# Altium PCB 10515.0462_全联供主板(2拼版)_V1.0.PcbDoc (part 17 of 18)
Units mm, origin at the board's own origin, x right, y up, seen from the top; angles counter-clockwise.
Board outline 282 x 198 mm, 2 copper layers (Top Layer, Bottom Layer); 716 components, 0 nets, 2364 pads, 1800 vias.
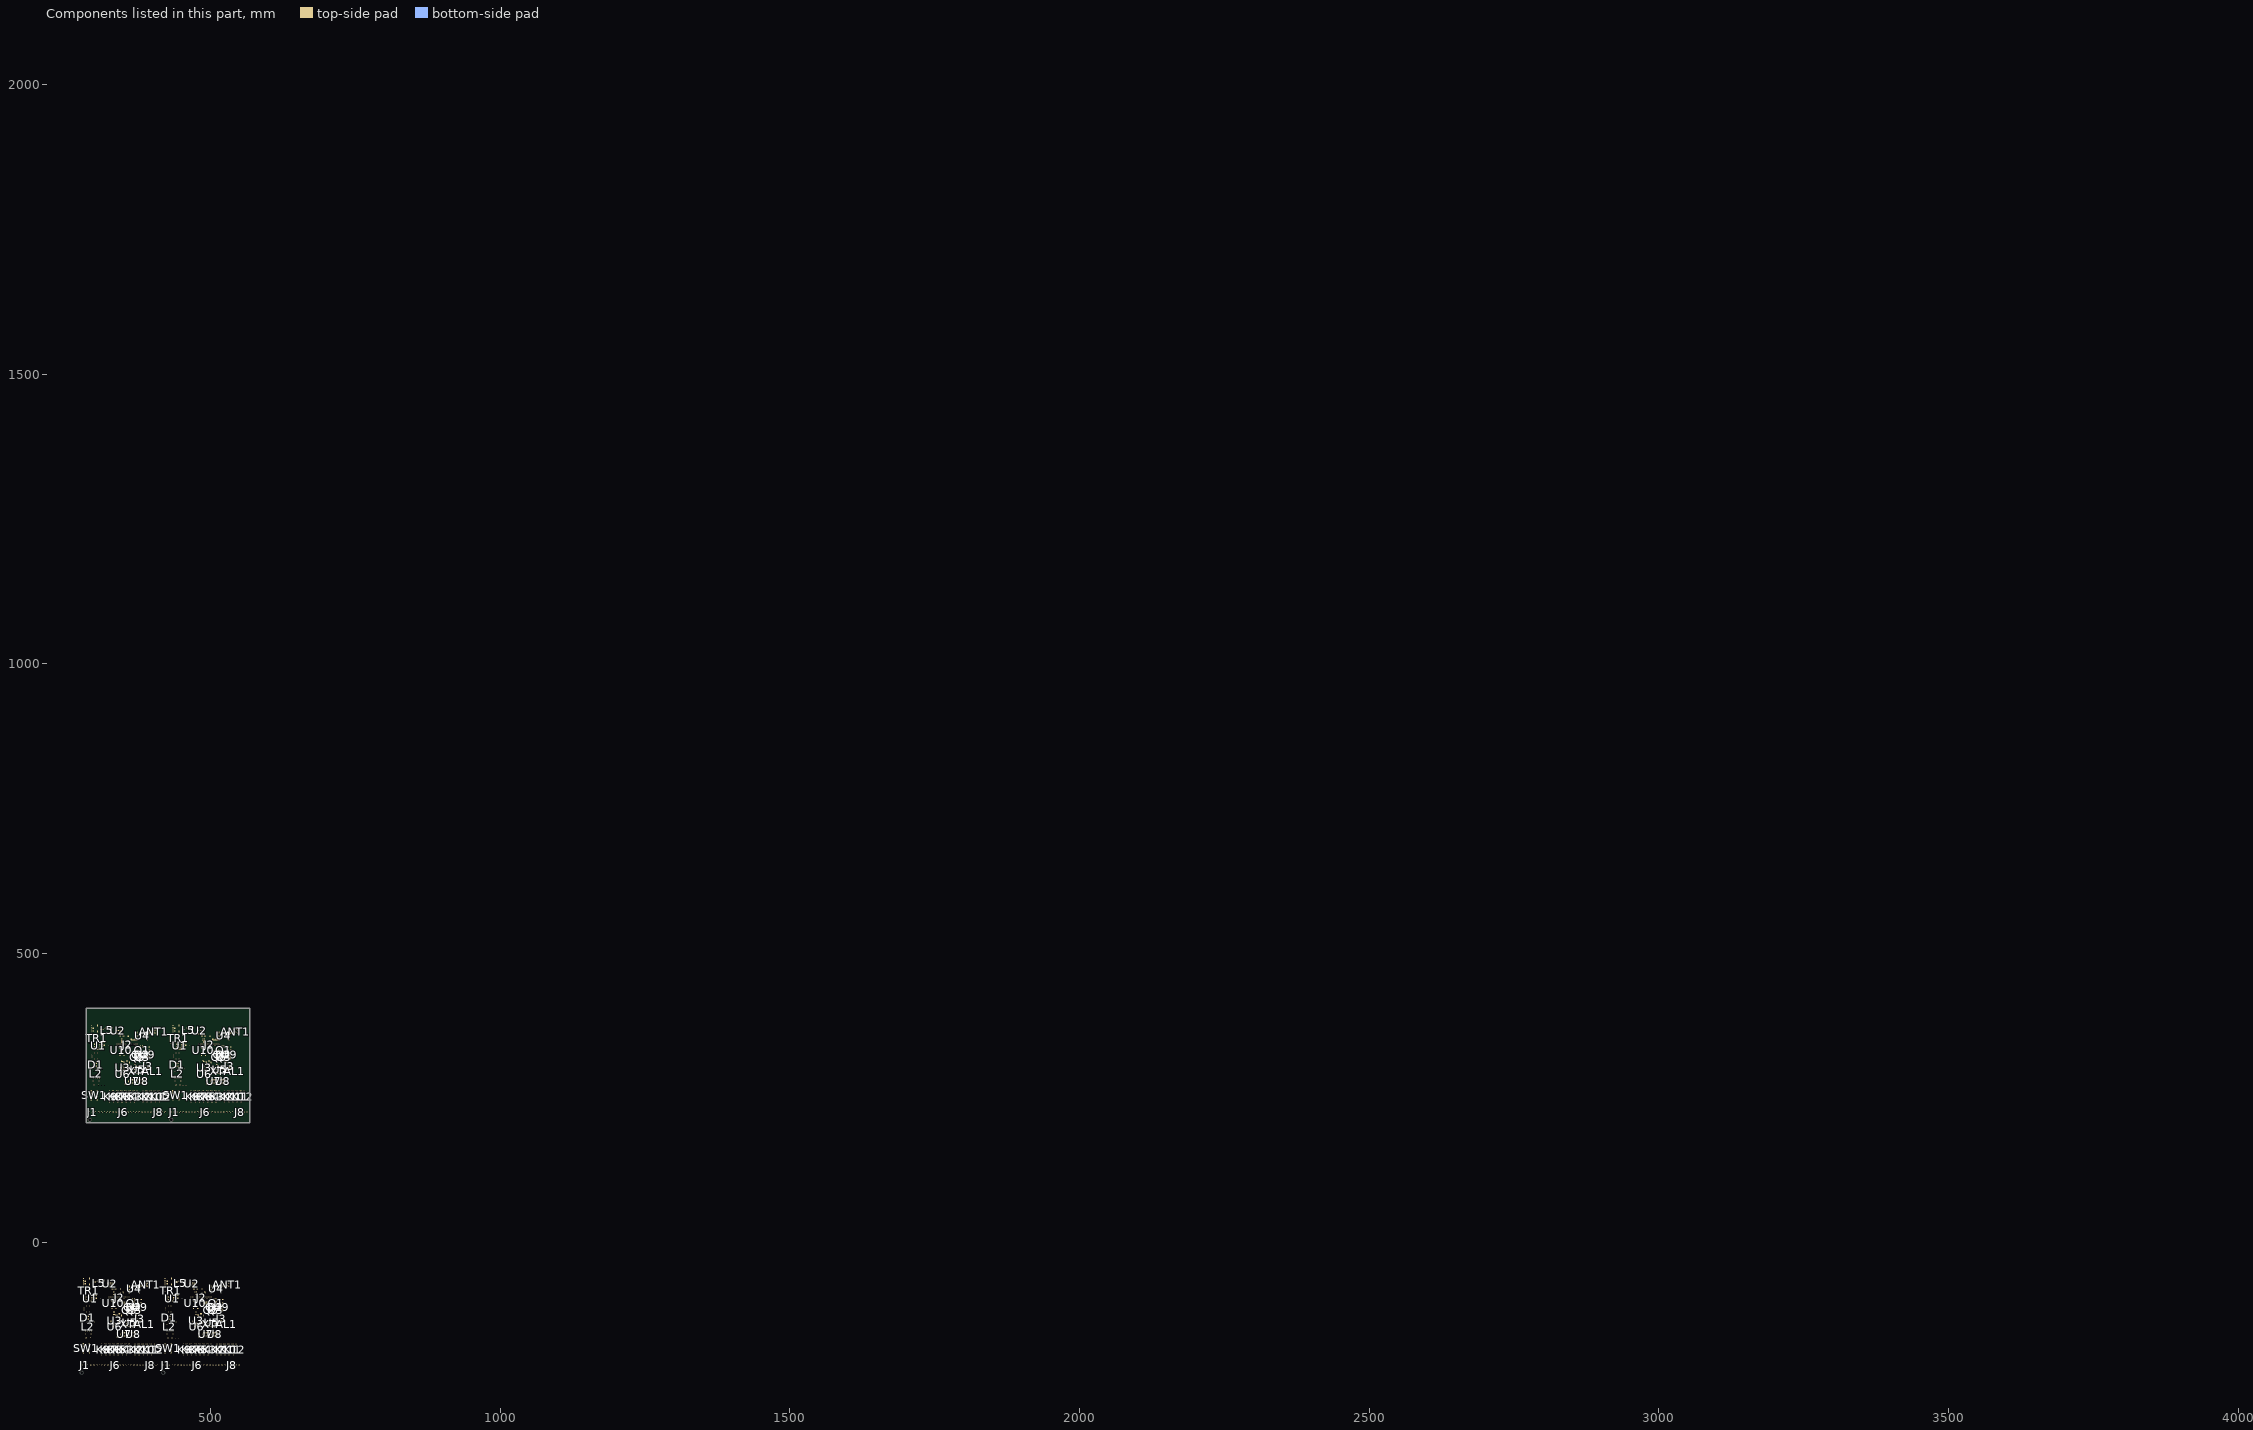
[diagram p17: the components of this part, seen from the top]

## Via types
v1: diameter 0.7, hole 0.4, Top Layer to Bottom Layer, tented both sides, 1800 vias

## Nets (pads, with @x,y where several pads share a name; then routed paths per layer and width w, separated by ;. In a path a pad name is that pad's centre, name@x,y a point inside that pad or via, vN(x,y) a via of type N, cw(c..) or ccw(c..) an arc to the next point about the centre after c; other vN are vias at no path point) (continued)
copper on no net: (continued)
  other v1: 333.609,-159.665 334.371,-159.665 474.609,-159.665 475.371,-159.665 333.99,-158.903 474.99,-158.903 371.943,-153.442 376.281,-153.442 512.943,-153.442 517.281,-153.442 326.731,-153.315 467.731,-153.315 379.837,-153.162 383.774,-153.162 520.837,-153.162 524.774,-153.162 332.319,-153.061 473.319,-153.061 338.923,-152.934 479.923,-152.934 369.403,-152.172 510.403,-152.172 324.191,-151.918 465.191,-151.918 345.527,-151.537 486.527,-151.537 386.441,-151.13 527.441,-151.13 374.63,-150.622 380.853,-150.622 515.63,-150.622 521.853,-150.622 338.923,-150.394 479.923,-150.394 330.688,-150.114 471.688,-150.114 345.801,-148.59 486.801,-148.59 338.181,-148.362 355.453,-148.362 372.959,-148.362 376.281,-148.362 479.181,-148.362 496.453,-148.362 513.959,-148.362 517.281,-148.362 368.387,-148.235 509.387,-148.235 327.259,-148.082 343.134,-148.082 352.405,-148.082 468.259,-148.082 484.134,-148.082 493.405,-148.082 348.575,-147.854 489.575,-147.854 379.563,-147.473 383.627,-147.473 520.563,-147.473 524.627,-147.473 323.175,-147.219 464.175,-147.219 385.806,-147.066 526.806,-147.066 348.067,-146.076 489.067,-146.076 345.527,-145.822 486.527,-145.822 328.021,-145.542 469.021,-145.542 350.373,-145.314 491.373,-145.314 354.437,-145.034 495.437,-145.034 341.229,-144.78 482.229,-144.78 367.01,-144.526 508.01,-144.526 345.166,-144.018 486.166,-144.018 339.939,-143.79 480.939,-143.79 340.955,-143.663 481.955,-143.663 324.338,-143.51 371.582,-143.51 465.338,-143.51 512.582,-143.51 344.511,-143.282 485.511,-143.282 386.167,-143.155 527.167,-143.155 341.737,-143.002 350.754,-143.014 366.375,-143.002 482.737,-143.002 491.754,-143.014 507.375,-143.002 377.297,-142.774 518.297,-142.774 368.151,-142.335 509.151,-142.335 355.818,-142.292 496.818,-142.292 327.747,-142.139 468.747,-142.139 380.091,-142.012 521.091,-142.012 348.341,-140.869 489.341,-140.869 352.913,-140.742 493.913,-140.742 331.303,-139.726 472.303,-139.726 357.485,-139.446 362.438,-139.446 498.485,-139.446 503.438,-139.446 323.83,-138.938 464.83,-138.938 338.415,-138.71 479.415,-138.71 341.971,-138.583 482.971,-138.583 359.009,-138.456 500.009,-138.456 361.168,-138.43 502.168,-138.43 356.469,-138.329 497.469,-138.329 377.424,-137.922 518.424,-137.922 331.303,-137.567 472.303,-137.567 380.98,-137.059 521.98,-137.059 357.993,-136.906 386.314,-136.906 498.993,-136.906 527.314,-136.906 361.93,-136.805 502.93,-136.805 356.469,-136.398 360.152,-136.398 497.469,-136.398 501.152,-136.398 323.175,-136.043 464.175,-136.043 357.866,-135.154 498.866,-135.154 342.987,-135.027 345.019,-135.027 483.987,-135.027 486.019,-135.027 361.295,-134.646 502.295,-134.646 323.683,-134.011 464.683,-134.011 345.928,-133.858 347.706,-133.858 486.928,-133.858 488.706,-133.858 356.703,-133.63 497.703,-133.63 359.751,-133.503 500.751,-133.503 344.15,-133.35 362.819,-133.35 485.15,-133.35 503.819,-133.35 353.548,-132.842 355.326,-132.842 494.548,-132.842 496.326,-132.842 353.929,-131.318 494.929,-131.318 370.378,-130.709 511.378,-130.709 365.867,-130.302 386.06,-130.302 506.867,-130.302 527.06,-130.302 364.47,-129.976 505.47,-129.976 347.198,-128.804 488.198,-128.804 376.154,-128.778 517.154,-128.778 353.655,-128.677 494.655,-128.677 346.182,-127.28 487.182,-127.28 284.587,-126.487 285.222,-126.487 425.587,-126.487 426.222,-126.487 323.175,-126.391 328.255,-126.391 464.175,-126.391 469.255,-126.391 381.742,-125.73 522.742,-125.73 365.232,-125.222 506.232,-125.222 386.167,-123.851 527.167,-123.851 377.805,-123.698 518.805,-123.698 327.386,-123.19 468.386,-123.19 365.486,-122.682 506.486,-122.682 382.103,-122.454 523.103,-122.454 336.784,-120.65 477.784,-120.65 327.513,-120.142 346.436,-120.142 468.513,-120.142 487.436,-120.142 337.673,-119.634 478.673,-119.634 341.463,-118.898 482.463,-118.898 342.88,-118.618 483.88,-118.618 327.513,-117.602 468.513,-117.602 340.447,-116.993 481.447,-116.993 322.941,-116.866 463.941,-116.866 336.383,-116.231 477.383,-116.231 338.923,-115.723 479.923,-115.723 343.007,-115.57 346.69,-115.57 484.007,-115.57 487.69,-115.57 382.123,-115.062 523.123,-115.062 327.005,-114.046 468.005,-114.046 385.659,-113.183 526.659,-113.183 323.068,-112.014 376.789,-112.014 464.068,-112.014 517.789,-112.014 381.869,-111.506 522.869,-111.506 336.657,-109.754 477.657,-109.754 326.878,-108.966 467.878,-108.966 373.614,-107.95 514.614,-107.95 322.667,-106.579 463.667,-106.579 358.501,-105.918 359.771,-105.918 499.501,-105.918 500.771,-105.918 327.239,-105.182 372.959,-105.182 468.239,-105.182 513.959,-105.182 382.123,-104.902 523.123,-104.902 386.167,-104.039 527.167,-104.039 335.514,-103.658 476.514,-103.658 322.941,-102.362 327.005,-102.362 336.657,-102.362 463.941,-102.362 468.005,-102.362 477.657,-102.362 359.009,-101.346 500.009,-101.346 361.783,-101.245 502.783,-101.245 382.377,-100.838 523.377,-100.838 380.579,-100.356 521.579,-100.356 373.467,-100.229 514.467,-100.229 327.239,-100.102 468.239,-100.102 336.657,-99.975 477.657,-99.975 322.667,-98.705 463.667,-98.705 382.611,-96.038 523.611,-96.038 380.853,-95.25 386.314,-95.25 521.853,-95.25 527.314,-95.25 362.565,-92.202 503.565,-92.202 377.023,-92.101 518.023,-92.101 366.355,-91.974 373.741,-91.974 507.355,-91.974 514.741,-91.974 381.087,-91.847 522.087,-91.847 369.804,-91.696 510.804,-91.696 379.055,-90.196 520.055,-90.196 325.989,-89.688 466.989,-89.688 329.271,-89.307 470.271,-89.307 346.436,-88.63 487.436,-88.63 345.227,-88.415 349.083,-88.418 486.227,-88.415 490.083,-88.418 323.83,-88.291 341.483,-88.291 464.83,-88.291 482.483,-88.291 350.5,-88.138 358.882,-88.138 371.074,-88.138 377.932,-88.138 491.5,-88.138 499.882,-88.138 512.074,-88.138 518.932,-88.138 355.687,-88.037 496.687,-88.037 348.067,-87.91 489.067,-87.91 345.846,-87.796 486.846,-87.796 361.275,-87.783 502.275,-87.783 353.929,-87.63 494.929,-87.63 342.245,-87.529 483.245,-87.529 350.099,-87.255 491.099,-87.255 379.964,-87.122 520.964,-87.122 337.399,-86.894 478.399,-86.894 327.894,-86.614 365.994,-86.614 468.894,-86.614 506.994,-86.614 371.943,-86.259 512.943,-86.259 362.184,-86.106 503.184,-86.106 339.451,-85.09 480.451,-85.09 323.957,-84.608 464.957,-84.608 380.091,-84.582 521.091,-84.582 346.436,-84.163 487.436,-84.163 371.074,-84.13 512.074,-84.13 363.835,-84.074 367.645,-84.074 504.835,-84.074 508.645,-84.074 335.875,-83.846 476.875,-83.846 344.912,-83.566 485.912,-83.566 380.071,-83.338 521.071,-83.338 326.243,-83.211 467.243,-83.211 339.578,-83.058 349.103,-83.058 480.578,-83.058 490.103,-83.058 354.056,-82.957 495.056,-82.957 329.291,-82.83 470.291,-82.83 303.764,-82.576 444.764,-82.576 344.912,-82.55 485.912,-82.55 302.621,-82.195 443.621,-82.195 350.607,-81.941 372.451,-81.941 491.607,-81.941 513.451,-81.941 303.637,-81.814 304.272,-81.814 444.637,-81.814 445.272,-81.814 352.532,-81.687 370.419,-81.687 493.532,-81.687 511.419,-81.687 302.958,-81.643 443.958,-81.643 335.26,-81.534 476.26,-81.534 347.559,-81.433 380.071,-81.433 488.559,-81.433 521.071,-81.433 339.431,-81.179 365.847,-81.179 480.431,-81.179 506.847,-81.179 336.784,-81.026 477.784,-81.026 302.494,-80.925 443.494,-80.925 355.58,-80.518 496.58,-80.518 363.073,-80.01 369.169,-80.01 504.073,-80.01 510.169,-80.01 349.083,-79.909 490.083,-79.909 365.232,-79.502 380.345,-79.502 506.232,-79.502 521.345,-79.502 323.576,-79.401 464.576,-79.401 327.005,-79.274 339.431,-79.274 468.005,-79.274 480.431,-79.274 347.198,-78.486 488.198,-78.486 375.499,-78.385 516.499,-78.385 355.687,-78.004 496.687,-78.004 350.246,-77.978 372.598,-77.978 491.246,-77.978 513.598,-77.978 377.023,-77.75 380.071,-77.75 518.023,-77.75 521.071,-77.75 339.832,-77.47 353.294,-77.47 370.439,-77.47 480.832,-77.47 494.294,-77.47 511.439,-77.47 373.614,-76.962 383.393,-76.962 387.457,-76.962 389.997,-76.962 391.902,-76.962 514.614,-76.962 524.393,-76.962 528.457,-76.962 530.997,-76.962 532.902,-76.962 385.151,-76.833 526.151,-76.833 344.003,-76.734 381.087,-76.734 485.003,-76.734 522.087,-76.734 386.568,-76.48 527.568,-76.48 336.784,-76.454 379.329,-76.454 477.784,-76.454 520.329,-76.454 362.565,-76.226 503.565,-76.226 376.007,-76.099 517.007,-76.099 367.264,-75.946 377.805,-75.946 508.264,-75.946 518.805,-75.946 347.051,-75.718 382.611,-75.718 387.691,-75.718 393.045,-75.718 488.051,-75.718 523.611,-75.718 528.691,-75.718 534.045,-75.718 341.737,-75.438 377.043,-75.438 482.737,-75.438 518.043,-75.438 378.44,-74.956 519.44,-74.956 351.389,-74.93 492.389,-74.93 382.631,-74.917 523.631,-74.917 380.579,-74.829 521.579,-74.829 354.163,-74.702 355.687,-74.702 495.163,-74.702 496.687,-74.702 387.076,-74.482 388.092,-74.482 528.076,-74.482 529.092,-74.482 374.884,-74.422 392.918,-74.422 515.884,-74.422 533.918,-74.422 364.089,-74.194 382.611,-74.194 505.089,-74.194 523.611,-74.194 369.911,-74.067 510.911,-74.067 378.44,-73.94 519.44,-73.94 332.72,-73.914 351.262,-73.914 473.72,-73.914 492.262,-73.914 373.467,-73.813 514.467,-73.813 349.23,-73.406 490.23,-73.406 332.085,-73.178 473.085,-73.178 382.814,-73.152 523.814,-73.152 338.923,-73.051 378.44,-73.051 392.771,-73.051 479.923,-73.051 519.44,-73.051 533.771,-73.051 375.349,-72.898 516.349,-72.898 374.483,-72.67 515.483,-72.67 341.971,-72.543 482.971,-72.543 371.836,-72.39 393.553,-72.39 512.836,-72.39 534.553,-72.39 390.113,-72.289 531.113,-72.289 336.149,-72.162 347.051,-72.162 477.149,-72.162 488.051,-72.162 391.247,-72.035 532.247,-72.035 351.897,-71.882 354.437,-71.882 365.232,-71.882 492.897,-71.882 495.437,-71.882 506.232,-71.882 322.944,-71.522 463.944,-71.522 390.113,-71.4 531.113,-71.4 356.596,-71.374 374.757,-71.374 497.596,-71.374 515.757,-71.374 334.351,-71.019 475.351,-71.019 392.283,-70.866 533.283,-70.866 382.611,-70.669 523.611,-70.669 393.279,-70.638 534.279,-70.638 375.9,-70.556 377.805,-70.556 516.9,-70.556 518.805,-70.556 374.991,-70.003 515.991,-70.003 377.023,-69.876 518.023,-69.876 336.276,-69.85 377.805,-69.85 477.276,-69.85 518.805,-69.85 382.585,-69.622 523.585,-69.622 386.949,-69.402 387.965,-69.402 527.949,-69.402 528.965,-69.402 378.694,-69.284 519.694,-69.284 318.496,-69.114 320.655,-69.114 459.496,-69.114 461.655,-69.114 334.859,-68.987 382.103,-68.987 475.859,-68.987 523.103,-68.987 371.328,-68.834 375.646,-68.834 380.345,-68.834 512.328,-68.834 516.646,-68.834 521.345,-68.834 363.815,-68.606 373.467,-68.606 504.815,-68.606 514.467,-68.606 378.547,-68.479 519.547,-68.479 343.007,-68.326 368.788,-68.326 387.584,-68.326 392.537,-68.326 393.553,-68.326 484.007,-68.326 509.788,-68.326 528.584,-68.326 533.537,-68.326 534.553,-68.326 358.227,-68.098 381.869,-68.098 499.227,-68.098 522.869,-68.098 355.179,-67.971 496.179,-67.971 332.974,-67.818 349.23,-67.818 379.71,-67.818 473.974,-67.818 490.23,-67.818 520.71,-67.818 335.875,-67.717 476.875,-67.717 360.259,-67.59 501.259,-67.59 320.318,-67.336 461.318,-67.336 392.537,-67.31 533.537,-67.31 383.119,-67.082 524.119,-67.082 366.883,-66.802 384.917,-66.802 386.695,-66.802 507.883,-66.802 525.917,-66.802 527.695,-66.802 390.231,-66.701 531.231,-66.701 379.055,-66.574 380.579,-66.574 520.055,-66.574 521.579,-66.574 321.798,-66.294 323.957,-66.294 326.116,-66.294 331.069,-66.294 333.228,-66.294 376.281,-66.294 462.798,-66.294 464.957,-66.294 467.116,-66.294 472.069,-66.294 474.228,-66.294 517.281,-66.294 328.255,-66.066 371.201,-66.066 392.771,-66.066 469.255,-66.066 512.201,-66.066 533.771,-66.066 387.691,-65.939 528.691,-65.939 356.596,-65.786 383.393,-65.786 497.596,-65.786 524.393,-65.786 341.971,-65.558 351.115,-65.558 482.971,-65.558 492.115,-65.558 364.597,-65.278 505.597,-65.278 376.281,-64.77 380.726,-64.77 517.281,-64.77 521.726,-64.77 386.167,-64.415 390.739,-64.415 527.167,-64.415 531.739,-64.415 382.885,-64.262 388.981,-64.262 523.885,-64.262 529.981,-64.262 379.329,-63.754 520.329,-63.754 347.238,276.93 348,276.93 488.238,276.93 489,276.93 347.619,277.692 488.619,277.692 385.572,283.153 389.91,283.153 526.572,283.153 530.91,283.153 340.36,283.28 481.36,283.28 393.466,283.433 397.403,283.433 534.466,283.433 538.403,283.433 345.948,283.534 486.948,283.534 352.552,283.661 493.552,283.661 383.032,284.423 524.032,284.423 337.82,284.677 478.82,284.677 359.156,285.058 500.156,285.058 400.07,285.465 541.07,285.465 388.259,285.973 394.482,285.973 529.259,285.973 535.482,285.973 352.552,286.201 493.552,286.201 344.317,286.481 485.317,286.481 359.43,288.005 500.43,288.005 351.81,288.233 369.082,288.233 386.588,288.233 389.91,288.233 492.81,288.233 510.082,288.233 527.588,288.233 530.91,288.233 382.016,288.36 523.016,288.36 340.888,288.513 356.763,288.513 366.034,288.513 481.888,288.513 497.763,288.513 507.034,288.513 362.204,288.741 503.204,288.741 393.192,289.122 397.256,289.122 534.192,289.122 538.256,289.122 336.804,289.376 477.804,289.376 399.435,289.529 540.435,289.529 361.696,290.519 502.696,290.519 359.156,290.773 500.156,290.773 341.65,291.053 482.65,291.053 364.002,291.281 505.002,291.281 368.066,291.561 509.066,291.561 354.858,291.816 495.858,291.816 380.639,292.069 521.639,292.069 358.795,292.577 499.795,292.577 353.568,292.805 494.568,292.805 354.584,292.932 495.584,292.932 337.967,293.085 385.211,293.085 478.967,293.085 526.211,293.085 358.14,293.313 499.14,293.313 399.796,293.44 540.796,293.44 364.383,293.581 505.383,293.581 355.366,293.593 380.004,293.593 496.366,293.593 521.004,293.593 390.926,293.821 531.926,293.821 381.78,294.26 522.78,294.26 369.447,294.303 510.447,294.303 341.376,294.456 482.376,294.456 393.72,294.583 534.72,294.583 361.97,295.726 502.97,295.726 366.542,295.853 507.542,295.853 344.932,296.869 485.932,296.869 371.114,297.149 376.067,297.149 512.114,297.149 517.067,297.149 337.459,297.657 478.459,297.657 352.044,297.885 493.044,297.885 355.6,298.012 496.6,298.012 372.638,298.139 513.638,298.139 374.797,298.165 515.797,298.165 370.098,298.266 511.098,298.266 391.053,298.673 532.053,298.673 344.932,299.028 485.932,299.028 394.609,299.536 535.609,299.536 371.622,299.689 399.943,299.689 512.622,299.689 540.943,299.689 375.559,299.79 516.559,299.79 370.098,300.197 373.781,300.197 511.098,300.197 514.781,300.197 336.804,300.552 477.804,300.552 371.495,301.441 512.495,301.441 356.616,301.568 358.648,301.568 497.616,301.568 499.648,301.568 374.924,301.949 515.924,301.949 337.312,302.584 478.312,302.584 359.557,302.737 361.335,302.737 500.557,302.737 502.335,302.737 370.332,302.965 511.332,302.965 373.38,303.092 514.38,303.092 357.779,303.245 376.448,303.245 498.779,303.245 517.448,303.245 367.177,303.753 368.955,303.753 508.177,303.753 509.955,303.753 367.558,305.277 508.558,305.277 384.007,305.886 525.007,305.886 379.496,306.293 399.689,306.293 520.496,306.293 540.689,306.293 378.099,306.62 519.099,306.62 360.827,307.791 501.827,307.791 389.783,307.817 530.783,307.817 367.284,307.918 508.284,307.918 359.811,309.315 500.811,309.315 298.216,310.108 298.851,310.108 439.216,310.108 439.851,310.108 336.804,310.204 341.884,310.204 477.804,310.204 482.884,310.204 395.371,310.865 536.371,310.865 378.861,311.373 519.861,311.373 399.796,312.744 540.796,312.744 391.434,312.897 532.434,312.897 341.015,313.405 482.015,313.405 379.115,313.913 520.115,313.913 395.732,314.141 536.732,314.141 350.413,315.945 491.413,315.945 341.142,316.453 360.065,316.453 482.142,316.453 501.065,316.453 351.302,316.961 492.302,316.961 355.092,317.697 496.092,317.697 356.509,317.977 497.509,317.977 341.142,318.993 482.142,318.993 354.076,319.602 495.076,319.602 336.57,319.729 477.57,319.729 350.012,320.364 491.012,320.364 352.552,320.872 493.552,320.872 356.636,321.025 360.319,321.025 497.636,321.025 501.319,321.025 395.752,321.533 536.752,321.533 340.634,322.549 481.634,322.549 399.288,323.412 540.288,323.412 336.697,324.581 390.418,324.581 477.697,324.581 531.418,324.581 395.498,325.089 536.498,325.089 350.286,326.841 491.286,326.841 340.507,327.629 481.507,327.629 387.243,328.645 528.243,328.645 336.296,330.016 477.296,330.016 372.13,330.677 373.4,330.677 513.13,330.677 514.4,330.677 340.868,331.413 386.588,331.413 481.868,331.413 527.588,331.413 395.752,331.693 536.752,331.693 399.796,332.556 540.796,332.556 349.143,332.937 490.143,332.937 336.57,334.233 340.634,334.233 350.286,334.233 477.57,334.233 481.634,334.233 491.286,334.233 372.638,335.249 513.638,335.249 375.412,335.35 516.412,335.35 396.006,335.757 537.006,335.757 394.208,336.239 535.208,336.239 387.096,336.366 528.096,336.366 340.868,336.493 481.868,336.493 350.286,336.62 491.286,336.62 336.296,337.89 477.296,337.89 396.24,340.557 537.24,340.557 394.482,341.345 399.943,341.345 535.482,341.345 540.943,341.345 376.194,344.393 517.194,344.393 390.652,344.494 531.652,344.494 379.984,344.621 387.37,344.621 520.984,344.621 528.37,344.621 394.716,344.748 535.716,344.748 383.433,344.899 524.433,344.899 392.684,346.399 533.684,346.399 339.618,346.907 480.618,346.907 342.9,347.288 483.9,347.288 360.065,347.965 501.065,347.965 358.856,348.18 362.712,348.177 499.856,348.18 503.712,348.177 337.459,348.304 355.112,348.304 478.459,348.304 496.112,348.304 364.129,348.457 372.511,348.457 384.703,348.457 391.561,348.457 505.129,348.457 513.511,348.457 525.703,348.457 532.561,348.457 369.316,348.558 510.316,348.558 361.696,348.685 502.696,348.685 359.475,348.799 500.475,348.799 374.904,348.812 515.904,348.812 367.558,348.965 508.558,348.965 355.874,349.066 496.874,349.066 363.728,349.34 504.728,349.34 393.593,349.473 534.593,349.473 351.028,349.701 492.028,349.701 341.523,349.981 379.623,349.981 482.523,349.981 520.623,349.981 385.572,350.336 526.572,350.336 375.813,350.489 516.813,350.489 353.08,351.505 494.08,351.505 337.586,351.987 478.586,351.987 393.72,352.013 534.72,352.013 360.065,352.432 501.065,352.432 384.703,352.465 525.703,352.465 377.464,352.521 381.274,352.521 518.464,352.521 522.274,352.521 349.504,352.749 490.504,352.749 358.541,353.029 499.541,353.029 393.7,353.257 534.7,353.257 339.872,353.384 480.872,353.384 353.207,353.537 362.732,353.537 494.207,353.537 503.732,353.537 367.685,353.638 508.685,353.638 342.92,353.765 483.92,353.765 317.393,354.019 458.393,354.019 358.541,354.045 499.541,354.045 316.25,354.4 457.25,354.4 364.236,354.654 386.08,354.654 505.236,354.654 527.08,354.654 317.266,354.781 317.901,354.781 458.266,354.781 458.901,354.781 366.161,354.908 384.048,354.908 507.161,354.908 525.048,354.908 316.587,354.952 457.587,354.952 348.889,355.061 489.889,355.061 361.188,355.162 393.7,355.162 502.188,355.162 534.7,355.162 353.06,355.416 379.476,355.416 494.06,355.416 520.476,355.416 350.413,355.569 491.413,355.569 316.123,355.67 457.123,355.67 369.209,356.077 510.209,356.077 376.702,356.585 382.798,356.585 517.702,356.585 523.798,356.585 362.712,356.686 503.712,356.686 378.861,357.093 393.974,357.093 519.861,357.093 534.974,357.093 337.205,357.194 478.205,357.194 340.634,357.321 353.06,357.321 481.634,357.321 494.06,357.321 360.827,358.109 501.827,358.109 389.128,358.21 530.128,358.21 369.316,358.591 510.316,358.591 363.875,358.617 386.227,358.617 504.875,358.617 527.227,358.617 390.652,358.845 393.7,358.845 531.652,358.845 534.7,358.845 353.461,359.125 366.923,359.125 384.068,359.125 494.461,359.125 507.923,359.125 525.068,359.125 387.243,359.633 397.022,359.633 401.086,359.633 403.626,359.633 405.531,359.633 528.243,359.633 538.022,359.633 542.086,359.633 544.626,359.633 546.531,359.633 398.78,359.763 539.78,359.763 357.632,359.861 394.716,359.861 498.632,359.861 535.716,359.861 400.197,360.115 541.197,360.115 350.413,360.141 392.958,360.141 491.413,360.141 533.958,360.141 376.194,360.369 517.194,360.369 389.636,360.496 530.636,360.496 380.893,360.649 391.434,360.649 521.893,360.649 532.434,360.649 360.68,360.877 396.24,360.877 401.32,360.877 406.674,360.877 501.68,360.877 537.24,360.877 542.32,360.877 547.674,360.877 355.366,361.157 390.672,361.157 496.366,361.157 531.672,361.157 392.069,361.639 533.069,361.639 365.018,361.665 396.26,361.679 506.018,361.665 537.26,361.679 394.208,361.766 535.208,361.766 367.792,361.893 369.316,361.893 508.792,361.893 510.316,361.893 400.705,362.114 401.721,362.114 541.705,362.114 542.721,362.114 388.513,362.173 406.547,362.173 529.513,362.173 547.547,362.173 377.718,362.401 396.24,362.401 518.718,362.401 537.24,362.401 383.54,362.528 524.54,362.528 392.069,362.655 533.069,362.655 346.349,362.681 364.891,362.681 487.349,362.681 505.891,362.681 387.096,362.782 528.096,362.782 362.859,363.189 503.859,363.189 345.714,363.417 486.714,363.417 396.443,363.443 537.443,363.443 352.552,363.544 392.069,363.544 406.4,363.544 493.552,363.544 533.069,363.544 547.4,363.544 388.978,363.697 529.978,363.697 388.112,363.925 529.112,363.925 355.6,364.052 496.6,364.052 385.465,364.205 407.182,364.205 526.465,364.205 548.182,364.205 403.741,364.306 544.741,364.306 349.778,364.433 360.68,364.433 490.778,364.433 501.68,364.433 404.876,364.56 545.876,364.56 365.526,364.713 368.066,364.713 378.861,364.713 506.526,364.713 509.066,364.713 519.861,364.713 336.573,365.074 477.573,365.074 403.741,365.195 544.741,365.195 370.225,365.221 388.386,365.221 511.225,365.221 529.386,365.221 347.98,365.576 488.98,365.576 405.912,365.729 546.912,365.729 396.24,365.927 537.24,365.927 406.908,365.957 547.908,365.957 389.529,366.039 391.434,366.039 530.529,366.039 532.434,366.039 388.62,366.592 529.62,366.592 390.652,366.719 531.652,366.719 349.905,366.745 391.434,366.745 490.905,366.745 532.434,366.745 396.213,366.973 537.213,366.973 400.578,367.194 401.594,367.194 541.578,367.194 542.594,367.194 392.323,367.311 533.323,367.311 332.125,367.481 334.284,367.481 473.125,367.481 475.284,367.481 348.488,367.608 395.732,367.608 489.488,367.608 536.732,367.608 384.957,367.761 389.275,367.761 393.974,367.761 525.957,367.761 530.275,367.761 534.974,367.761 377.444,367.989 387.096,367.989 518.444,367.989 528.096,367.989 392.176,368.116 533.176,368.116 356.636,368.269 382.417,368.269 401.213,368.269 406.166,368.269 407.182,368.269 497.636,368.269 523.417,368.269 542.213,368.269 547.166,368.269 548.182,368.269 371.856,368.497 395.498,368.497 512.856,368.497 536.498,368.497 368.808,368.624 509.808,368.624 346.603,368.777 362.859,368.777 393.339,368.777 487.603,368.777 503.859,368.777 534.339,368.777 349.504,368.878 490.504,368.878 373.888,369.005 514.888,369.005 333.947,369.259 474.947,369.259 406.166,369.285 547.166,369.285 396.748,369.513 537.748,369.513 380.512,369.793 398.546,369.793 400.324,369.793 521.512,369.793 539.546,369.793 541.324,369.793 403.86,369.894 544.86,369.894 392.684,370.021 394.208,370.021 533.684,370.021 535.208,370.021 335.427,370.301 337.586,370.301 339.745,370.301 344.698,370.301 346.857,370.301 389.91,370.301 476.427,370.301 478.586,370.301 480.745,370.301 485.698,370.301 487.857,370.301 530.91,370.301 341.884,370.529 384.83,370.529 406.4,370.529 482.884,370.529 525.83,370.529 547.4,370.529 401.32,370.656 542.32,370.656 370.225,370.809 397.022,370.809 511.225,370.809 538.022,370.809 355.6,371.037 364.744,371.037 496.6,371.037 505.744,371.037 378.226,371.317 519.226,371.317 389.91,371.825 394.355,371.825 530.91,371.825 535.355,371.825 399.796,372.18 404.368,372.18 540.796,372.18 545.368,372.18 396.514,372.333 402.61,372.333 537.514,372.333 543.61,372.333 392.958,372.841 533.958,372.841

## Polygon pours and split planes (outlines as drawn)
no net on Top Layer "Top Layer-No Net" (hatched 90Degree grid 0.508 track 0.508, remove dead copper, pour order 1000): 547.928,372.942 493.445,372.942 492.81,372.307 492.81,352.368 490.397,349.955 490.397,345.51 490.016,345.129 477.189,345.129 476.808,344.748 476.808,283.661 478.078,282.391 539.927,282.645 541.324,284.042 541.324,342.589 539.419,344.494 536.498,344.494 535.99,345.002 535.99,358.591 536.752,359.353 547.166,359.353 548.563,360.75 548.563,372.307
no net on Top Layer "Top Layer-No Net" (hatched 90Degree grid 0.508 track 0.508, remove dead copper, pour order 1001): 473.125,367.318 473.125,367.608 473.633,368.116 476.427,370.91 484.555,370.91 490.016,370.91 490.905,370.021 491.794,369.132 491.794,362.782 491.794,353.257 489.889,351.352 489.381,350.844 489.381,347.034 489.381,344.406 489.37,344.395 488.863,344.901 476.961,344.901 476.961,365.677 476.3,366.338 473.125,366.338 473.107,366.356 473.107,367.464
no net on Top Layer "Top Layer-No Net" (hatched 90Degree grid 0.508 track 0.508, remove dead copper, pour order 1000): 406.928,372.942 352.445,372.942 351.81,372.307 351.81,352.368 349.397,349.955 349.397,345.51 349.016,345.129 336.189,345.129 335.808,344.748 335.808,283.661 337.078,282.391 398.927,282.645 400.324,284.042 400.324,342.589 398.419,344.494 395.498,344.494 394.99,345.002 394.99,358.591 395.752,359.353 406.166,359.353 407.563,360.75 407.563,372.307
no net on Top Layer "Top Layer-No Net" (hatched 90Degree grid 0.508 track 0.508, remove dead copper, pour order 1001): 332.125,367.318 332.125,367.608 332.633,368.116 335.427,370.91 343.555,370.91 349.016,370.91 349.905,370.021 350.794,369.132 350.794,362.782 350.794,353.257 348.889,351.352 348.381,350.844 348.381,347.034 348.381,344.406 348.37,344.395 347.863,344.901 335.961,344.901 335.961,365.677 335.3,366.338 332.125,366.338 332.107,366.356 332.107,367.464
no net on Top Layer "Top Layer-No Net" (hatched 90Degree grid 0.508 track 0.508, remove dead copper, pour order 1000): 534.299,-63.653 479.816,-63.653 479.181,-64.288 479.181,-84.227 476.768,-86.64 476.768,-91.085 476.387,-91.466 463.56,-91.466 463.179,-91.847 463.179,-152.934 464.449,-154.204 526.298,-153.95 527.695,-152.553 527.695,-94.006 525.79,-92.101 522.869,-92.101 522.361,-91.593 522.361,-78.004 523.123,-77.242 533.537,-77.242 534.934,-75.845 534.934,-64.288
no net on Top Layer "Top Layer-No Net" (hatched 90Degree grid 0.508 track 0.508, remove dead copper, pour order 1001): 459.496,-69.278 459.496,-68.987 460.004,-68.479 462.798,-65.685 470.926,-65.685 476.387,-65.685 477.276,-66.574 478.165,-67.463 478.165,-73.813 478.165,-83.338 476.26,-85.243 475.752,-85.751 475.752,-89.561 475.752,-92.189 475.741,-92.2 475.235,-91.694 463.332,-91.694 463.332,-70.918 462.671,-70.257 459.496,-70.257 459.478,-70.239 459.478,-69.132
no net on Top Layer "Top Layer-No Net" (hatched 90Degree grid 0.508 track 0.508, remove dead copper, pour order 1000): 393.299,-63.653 338.816,-63.653 338.181,-64.288 338.181,-84.227 335.768,-86.64 335.768,-91.085 335.387,-91.466 322.56,-91.466 322.179,-91.847 322.179,-152.934 323.449,-154.204 385.298,-153.95 386.695,-152.553 386.695,-94.006 384.79,-92.101 381.869,-92.101 381.361,-91.593 381.361,-78.004 382.123,-77.242 392.537,-77.242 393.934,-75.845 393.934,-64.288
no net on Top Layer "Top Layer-No Net" (hatched 90Degree grid 0.508 track 0.508, remove dead copper, pour order 1001): 318.496,-69.278 318.496,-68.987 319.004,-68.479 321.798,-65.685 329.926,-65.685 335.387,-65.685 336.276,-66.574 337.165,-67.463 337.165,-73.813 337.165,-83.338 335.26,-85.243 334.752,-85.751 334.752,-89.561 334.752,-92.189 334.741,-92.2 334.235,-91.694 322.332,-91.694 322.332,-70.918 321.671,-70.257 318.496,-70.257 318.478,-70.239 318.478,-69.132
no net on Bottom Layer "Top Layer-No Net" (hatched 90Degree grid 0.508 track 0.508, remove dead copper, pour order 1002): 547.928,372.942 493.445,372.942 493.064,372.561 493.064,352.622 490.397,349.955 490.397,345.51 490.016,345.129 477.189,345.129 476.808,344.748 476.808,283.788 478.078,282.518 540.054,282.518 541.324,283.788 541.324,342.589 539.419,344.494 536.498,344.494 535.99,345.002 535.99,358.591 536.752,359.353 547.166,359.353 548.563,360.75 548.563,372.307
no net on Bottom Layer "Top Layer-No Net" (hatched 90Degree grid 0.508 track 0.508, remove dead copper, pour order 1003): 473.125,367.318 473.125,367.608 473.633,368.116 476.427,370.91 484.555,370.91 490.016,370.91 490.905,370.021 491.794,369.132 491.794,362.782 491.794,353.257 489.889,351.352 489.381,350.844 489.381,347.034 489.381,344.406 489.37,344.395 488.863,344.901 476.961,344.901 476.961,365.677 476.3,366.338 473.125,366.338 473.107,366.356 473.107,367.464
no net on Bottom Layer "Top Layer-No Net" (hatched 90Degree grid 0.508 track 0.508, remove dead copper, pour order 1002): 406.928,372.942 352.445,372.942 352.064,372.561 352.064,352.622 349.397,349.955 349.397,345.51 349.016,345.129 336.189,345.129 335.808,344.748 335.808,283.788 337.078,282.518 399.054,282.518 400.324,283.788 400.324,342.589 398.419,344.494 395.498,344.494 394.99,345.002 394.99,358.591 395.752,359.353 406.166,359.353 407.563,360.75 407.563,372.307
no net on Bottom Layer "Top Layer-No Net" (hatched 90Degree grid 0.508 track 0.508, remove dead copper, pour order 1003): 332.125,367.318 332.125,367.608 332.633,368.116 335.427,370.91 343.555,370.91 349.016,370.91 349.905,370.021 350.794,369.132 350.794,362.782 350.794,353.257 348.889,351.352 348.381,350.844 348.381,347.034 348.381,344.406 348.37,344.395 347.863,344.901 335.961,344.901 335.961,365.677 335.3,366.338 332.125,366.338 332.107,366.356 332.107,367.464
no net on Bottom Layer "Top Layer-No Net" (hatched 90Degree grid 0.508 track 0.508, remove dead copper, pour order 1002): 534.299,-63.653 479.816,-63.653 479.435,-64.034 479.435,-83.973 476.768,-86.64 476.768,-91.085 476.387,-91.466 463.56,-91.466 463.179,-91.847 463.179,-152.807 464.449,-154.077 526.425,-154.077 527.695,-152.807 527.695,-94.006 525.79,-92.101 522.869,-92.101 522.361,-91.593 522.361,-78.004 523.123,-77.242 533.537,-77.242 534.934,-75.845 534.934,-64.288
no net on Bottom Layer "Top Layer-No Net" (hatched 90Degree grid 0.508 track 0.508, remove dead copper, pour order 1003): 459.496,-69.278 459.496,-68.987 460.004,-68.479 462.798,-65.685 470.926,-65.685 476.387,-65.685 477.276,-66.574 478.165,-67.463 478.165,-73.813 478.165,-83.338 476.26,-85.243 475.752,-85.751 475.752,-89.561 475.752,-92.189 475.741,-92.2 475.235,-91.694 463.332,-91.694 463.332,-70.918 462.671,-70.257 459.496,-70.257 459.478,-70.239 459.478,-69.132
no net on Bottom Layer "Top Layer-No Net" (hatched 90Degree grid 0.508 track 0.508, remove dead copper, pour order 1002): 393.299,-63.653 338.816,-63.653 338.435,-64.034 338.435,-83.973 335.768,-86.64 335.768,-91.085 335.387,-91.466 322.56,-91.466 322.179,-91.847 322.179,-152.807 323.449,-154.077 385.425,-154.077 386.695,-152.807 386.695,-94.006 384.79,-92.101 381.869,-92.101 381.361,-91.593 381.361,-78.004 382.123,-77.242 392.537,-77.242 393.934,-75.845 393.934,-64.288
no net on Bottom Layer "Top Layer-No Net" (hatched 90Degree grid 0.508 track 0.508, remove dead copper, pour order 1003): 318.496,-69.278 318.496,-68.987 319.004,-68.479 321.798,-65.685 329.926,-65.685 335.387,-65.685 336.276,-66.574 337.165,-67.463 337.165,-73.813 337.165,-83.338 335.26,-85.243 334.752,-85.751 334.752,-89.561 334.752,-92.189 334.741,-92.2 334.235,-91.694 322.332,-91.694 322.332,-70.918 321.671,-70.257 318.496,-70.257 318.478,-70.239 318.478,-69.132

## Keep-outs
Keep-Out Layer:
  circle w0.127: c440.008,400.708 r2
  circle w0.127: c554.024,212.708 r2
  circle w0.127: c553.008,400.708 r2
  circle w0.127: c299.008,400.708 r2
  circle w0.127: c413.024,212.708 r2
  circle w0.127: c412.008,400.708 r2
  circle w0.127: c426.379,-35.887 r2
  circle w0.127: c540.395,-223.887 r2
  circle w0.127: c539.379,-35.887 r2
  circle w0.127: c285.379,-35.887 r2
  circle w0.127: c399.395,-223.887 r2
  circle w0.127: c398.379,-35.887 r2
  circle w0.127: c3148.858,948.974 r0.85
  circle w0.127: c3148.858,966.045 r1
  circle w0.127: c3192.858,966.045 r1
  circle w0.127: c3158.858,966.545 r0.3
  circle w0.127: c3160.858,966.545 r0.3
  circle w0.127: c3162.858,966.545 r0.3
  circle w0.127: c3164.858,966.545 r0.3
  circle w0.127: c3166.858,966.545 r0.3
  circle w0.127: c3168.858,966.545 r0.3
  circle w0.127: c3170.858,966.545 r0.3
  circle w0.127: c3172.858,966.545 r0.3
  circle w0.127: c3174.858,966.545 r0.3
  circle w0.127: c3176.858,966.545 r0.3
  circle w0.127: c3178.858,966.545 r0.3
  circle w0.127: c3180.858,966.545 r0.3
  circle w0.127: c3273.858,956.045 r1.3
  circle w0.127: c3253.858,956.045 r1.3
  circle w0.127: c3273.858,956.045 r1.292
  circle w0.127: c3253.858,956.045 r1.292
  circle w0.127: c3273.858,956.045 r1.093
  circle w0.127: c3253.858,956.045 r1.093
  circle w0.127: c3246.787,948.974 r1
  circle w0.127: c3280.929,948.974 r1
  circle w0.127: c3275.608,954.295 r0.25
  circle w0.127: c3272.108,954.295 r0.25
  circle w0.127: c3255.608,954.295 r0.25
  circle w0.127: c3252.108,954.295 r0.25
  circle w0.127: c3272.108,954.295 r0.05
  circle w0.127: c3275.608,954.295 r0.05
  circle w0.127: c3252.108,954.295 r0.05
  circle w0.127: c3255.608,954.295 r0.05
  circle w0.127: c3263.858,966.045 r1
  circle w0.127: c3275.608,957.795 r0.25
  circle w0.127: c3272.108,957.795 r0.25
  circle w0.127: c3255.608,957.795 r0.25
  circle w0.127: c3252.108,957.795 r0.25
  circle w0.127: c3275.608,957.795 r0.05
  circle w0.127: c3272.108,957.795 r0.05
  circle w0.127: c3255.608,957.795 r0.05
  circle w0.127: c3252.108,957.795 r0.05
  circle w0.127: c3822.974,1486.311 r0.85
  circle w0.127: c3822.974,1503.382 r1
  circle w0.127: c3866.974,1503.382 r1
  circle w0.127: c3832.974,1503.882 r0.3
  circle w0.127: c3834.974,1503.882 r0.3
  circle w0.127: c3836.974,1503.882 r0.3
  circle w0.127: c3838.974,1503.882 r0.3
  circle w0.127: c3840.974,1503.882 r0.3
  circle w0.127: c3842.974,1503.882 r0.3
  circle w0.127: c3844.974,1503.882 r0.3
  circle w0.127: c3846.974,1503.882 r0.3
  circle w0.127: c3848.974,1503.882 r0.3
  circle w0.127: c3850.974,1503.882 r0.3
  circle w0.127: c3852.974,1503.882 r0.3
  circle w0.127: c3854.974,1503.882 r0.3
  circle w0.127: c3947.974,1493.382 r1.3
  circle w0.127: c3927.974,1493.382 r1.3
  circle w0.127: c3947.974,1493.382 r1.292
  circle w0.127: c3927.974,1493.382 r1.292
  circle w0.127: c3947.974,1493.382 r1.093
  circle w0.127: c3927.974,1493.382 r1.093
  circle w0.127: c3920.903,1486.311 r1
  circle w0.127: c3955.045,1486.311 r1
  circle w0.127: c3949.724,1491.632 r0.25
  circle w0.127: c3946.224,1491.632 r0.25
  circle w0.127: c3929.724,1491.632 r0.25
  circle w0.127: c3926.224,1491.632 r0.25
  circle w0.127: c3946.224,1491.632 r0.05
  circle w0.127: c3949.724,1491.632 r0.05
  circle w0.127: c3926.224,1491.632 r0.05
  circle w0.127: c3929.724,1491.632 r0.05
  circle w0.127: c3937.974,1503.382 r1
  circle w0.127: c3949.724,1495.132 r0.25
  circle w0.127: c3946.224,1495.132 r0.25
  circle w0.127: c3929.724,1495.132 r0.25
  circle w0.127: c3926.224,1495.132 r0.25
  circle w0.127: c3949.724,1495.132 r0.05
  circle w0.127: c3946.224,1495.132 r0.05
  circle w0.127: c3929.724,1495.132 r0.05
  circle w0.127: c3926.224,1495.132 r0.05
  circle w0.152: c1448.817,2044.74 r1
  circle w0.152: c1465.888,2027.669 r1
  circle w0.152: c1431.746,2027.669 r1
  circle w0.152: c1377.817,2044.74 r1
  circle w0.152: c1333.817,2044.74 r1
  circle w0.152: c1333.817,2027.669 r0.85
  pour cut-out: 478.586,359.226 481.507,359.226 481.507,363.163 480.999,363.671 479.475,363.671 478.967,363.163 478.967,359.607
  pour cut-out: 337.586,359.226 340.507,359.226 340.507,363.163 339.999,363.671 338.475,363.671 337.967,363.163 337.967,359.607
  pour cut-out: 464.957,-77.369 467.878,-77.369 467.878,-73.432 467.37,-72.924 465.846,-72.924 465.338,-73.432 465.338,-76.988
  pour cut-out: 323.957,-77.369 326.878,-77.369 326.878,-73.432 326.37,-72.924 324.846,-72.924 324.338,-73.432 324.338,-76.988
  lines w0.127: 3156.358,965.545 3156.358,964.945 3156.858,964.945 3156.858,968.445 3156.358,968.445 3156.358,967.845 ; 3156.858,965.545 3155.858,965.545 3155.858,963.645 3183.858,963.645 3183.858,965.545 3182.858,965.545 ; 3156.858,967.845 3155.858,967.845 3155.858,969.045 3183.858,969.045 3183.858,967.845 3182.858,967.845 ; 3183.358,965.545 3183.358,964.945 3182.858,964.945 3182.858,968.445 3183.358,968.445 3183.358,967.845 ; 3251.933,953.795 3251.933,951.345 3253.283,951.345 3253.283,953.795 ; 3251.933,958.295 3251.933,960.745 3253.283,960.745 3253.283,958.295 ; 3252.233,953.295 3252.983,953.295 ; 3252.233,953.395 3252.983,953.395 ; 3252.233,953.795 3252.233,952.845 3252.983,952.845 3252.983,953.795 ; 3252.233,958.295 3252.233,959.245 3252.983,959.245 3252.983,958.295 ; 3252.233,958.695 3252.983,958.695 ; 3252.233,958.795 3252.983,958.795 ; 3254.433,953.795 3254.433,951.345 3255.783,951.345 3255.783,953.795 ; 3254.433,958.295 3254.433,960.745 3255.783,960.745 3255.783,958.295 ; 3254.733,953.295 3255.483,953.295 ; 3254.733,953.395 3255.483,953.395 ; 3254.733,953.795 3254.733,952.845 3255.483,952.845 3255.483,953.795 ; 3254.733,958.295 3254.733,959.245 3255.483,959.245 3255.483,958.295 ; 3254.733,958.695 3255.483,958.695 ; 3254.733,958.795 3255.483,958.795 ; 3271.933,953.795 3271.933,951.345 3273.283,951.345 3273.283,953.795 ; 3271.933,958.295 3271.933,960.745 3273.283,960.745 3273.283,958.295 ; 3272.233,953.295 3272.983,953.295 ; 3272.233,953.395 3272.983,953.395 ; 3272.233,953.795 3272.233,952.845 3272.983,952.845 3272.983,953.795 ; 3272.233,958.295 3272.233,959.245 3272.983,959.245 3272.983,958.295 ; 3272.233,958.695 3272.983,958.695 ; 3272.233,958.795 3272.983,958.795 ; 3274.433,953.795 3274.433,951.345 3275.783,951.345 3275.783,953.795 ; 3274.433,958.295 3274.433,960.745 3275.783,960.745 3275.783,958.295 ; 3274.733,953.295 3275.483,953.295 ; 3274.733,953.395 3275.483,953.395 ; 3274.733,953.795 3274.733,952.845 3275.483,952.845 3275.483,953.795 ; 3274.733,958.295 3274.733,959.245 3275.483,959.245 3275.483,958.295 ; 3274.733,958.695 3275.483,958.695 ; 3274.733,958.795 3275.483,958.795 ; 3830.474,1502.882 3830.474,1502.282 3830.974,1502.282 3830.974,1505.782 3830.474,1505.782 3830.474,1505.182 ; 3830.974,1502.882 3829.974,1502.882 3829.974,1500.982 3857.974,1500.982 3857.974,1502.882 3856.974,1502.882 ; 3830.974,1505.182 3829.974,1505.182 3829.974,1506.382 3857.974,1506.382 3857.974,1505.182 3856.974,1505.182 ; 3857.474,1502.882 3857.474,1502.282 3856.974,1502.282 3856.974,1505.782 3857.474,1505.782 3857.474,1505.182 ; 3926.049,1491.132 3926.049,1488.682 3927.399,1488.682 3927.399,1491.132 ; 3926.049,1495.632 3926.049,1498.082 3927.399,1498.082 3927.399,1495.632 ; 3926.349,1490.632 3927.099,1490.632 ; 3926.349,1490.732 3927.099,1490.732 ; 3926.349,1491.132 3926.349,1490.182 3927.099,1490.182 3927.099,1491.132 ; 3926.349,1495.632 3926.349,1496.582 3927.099,1496.582 3927.099,1495.632 ; 3926.349,1496.032 3927.099,1496.032 ; 3926.349,1496.132 3927.099,1496.132 ; 3928.549,1491.132 3928.549,1488.682 3929.899,1488.682 3929.899,1491.132 ; 3928.549,1495.632 3928.549,1498.082 3929.899,1498.082 3929.899,1495.632 ; 3928.849,1490.632 3929.599,1490.632 ; 3928.849,1490.732 3929.599,1490.732 ; 3928.849,1491.132 3928.849,1490.182 3929.599,1490.182 3929.599,1491.132 ; 3928.849,1495.632 3928.849,1496.582 3929.599,1496.582 3929.599,1495.632 ; 3928.849,1496.032 3929.599,1496.032 ; 3928.849,1496.132 3929.599,1496.132 ; 3946.049,1491.132 3946.049,1488.682 3947.399,1488.682 3947.399,1491.132 ; 3946.049,1495.632 3946.049,1498.082 3947.399,1498.082 3947.399,1495.632 ; 3946.349,1490.632 3947.099,1490.632 ; 3946.349,1490.732 3947.099,1490.732 ; 3946.349,1491.132 3946.349,1490.182 3947.099,1490.182 3947.099,1491.132 ; 3946.349,1495.632 3946.349,1496.582 3947.099,1496.582 3947.099,1495.632 ; 3946.349,1496.032 3947.099,1496.032 ; 3946.349,1496.132 3947.099,1496.132 ; 3948.549,1491.132 3948.549,1488.682 3949.899,1488.682 3949.899,1491.132 ; 3948.549,1495.632 3948.549,1498.082 3949.899,1498.082 3949.899,1495.632 ; 3948.849,1490.632 3949.599,1490.632 ; 3948.849,1490.732 3949.599,1490.732 ; 3948.849,1491.132 3948.849,1490.182 3949.599,1490.182 3949.599,1491.132 ; 3948.849,1495.632 3948.849,1496.582 3949.599,1496.582 3949.599,1495.632 ; 3948.849,1496.032 3949.599,1496.032 ; 3948.849,1496.132 3949.599,1496.132 ; 412.379,-228.887 553.379,-228.887 553.379,-217.887 553.379,-41.887 553.379,-30.887 412.379,-30.887 ; 412.379,-228.887 412.379,-217.887 ; 412.379,-228.887 271.379,-228.887 271.379,-217.887 271.379,-41.887 271.379,-30.887 412.379,-30.887 ; 412.379,-228.887 412.379,-217.887 ; 412.379,-217.887 412.379,-41.887 ; 412.379,-217.887 412.379,-41.887 ; 412.379,-41.887 412.379,-30.887 ; 412.379,-41.887 412.379,-30.887 ; 426.008,207.708 567.008,207.708 567.008,218.708 567.008,394.708 567.008,405.708 426.008,405.708 ; 426.008,207.708 426.008,218.708 ; 426.008,207.708 285.008,207.708 285.008,218.708 285.008,394.708 285.008,405.708 426.008,405.708 ; 426.008,207.708 426.008,218.708 ; 426.008,218.708 426.008,394.708 ; 426.008,218.708 426.008,394.708 ; 426.008,394.708 426.008,405.708 ; 426.008,394.708 426.008,405.708 ; 3143.858,945.045 3143.858,970.045 3283.858,970.045 3283.858,945.045 3143.858,945.045 ; 3157.458,964.145 3182.258,964.145 3182.258,967.645 3179.733,967.645 3179.733,968.545 3159.983,968.545 3159.983,967.645 3157.458,967.645 3157.458,964.145 ; 3251.608,953.995 ccw(c3251.808,953.995) 3251.808,953.795 3255.908,953.795 ccw(c3255.908,953.995) 3256.108,953.995 3256.108,958.095 ccw(c3255.908,958.095) 3255.908,958.295 3251.808,958.295 ccw(c3251.808,958.095) 3251.608,958.095 3251.608,953.995 ; 3271.608,953.995 ccw(c3271.808,953.995) 3271.808,953.795 3275.908,953.795 ccw(c3275.908,953.995) 3276.108,953.995 3276.108,958.095 ccw(c3275.908,958.095) 3275.908,958.295 3271.808,958.295 ccw(c3271.808,958.095) 3271.608,958.095 3271.608,953.995 ; 3817.974,1482.382 3817.974,1507.382 3957.974,1507.382 3957.974,1482.382 3817.974,1482.382 ; 3831.574,1501.482 3856.374,1501.482 3856.374,1504.982 3853.849,1504.982 3853.849,1505.882 3834.099,1505.882 3834.099,1504.982 3831.574,1504.982 3831.574,1501.482 ; 3925.724,1491.332 ccw(c3925.924,1491.332) 3925.924,1491.132 3930.024,1491.132 ccw(c3930.024,1491.332) 3930.224,1491.332 3930.224,1495.432 ccw(c3930.024,1495.432) 3930.024,1495.632 3925.924,1495.632 ccw(c3925.924,1495.432) 3925.724,1495.432 3925.724,1491.332 ; 3945.724,1491.332 ccw(c3945.924,1491.332) 3945.924,1491.132 3950.024,1491.132 ccw(c3950.024,1491.332) 3950.224,1491.332 3950.224,1495.432 ccw(c3950.024,1495.432) 3950.024,1495.632 3945.924,1495.632 ccw(c3945.924,1495.432) 3945.724,1495.432 3945.724,1491.332
  lines w0.152: 1328.817,2023.74 1468.817,2023.74 1468.817,2048.74 1328.817,2048.74 1328.817,2023.74
  lines w1.2: 274.808,-80.036 280.777,-80.036 285.476,-84.735 303.129,-84.735 306.304,-87.91 306.304,-99.721 ; 279.634,-214.148 279.634,-205.893 ; 287.635,-134.519 287.635,-128.677 ; 288.437,356.559 294.406,356.559 299.105,351.86 316.758,351.86 319.933,348.685 319.933,336.874 ; 288.524,-155.728 288.524,-164.872 292.842,-169.19 ; 293.263,222.447 293.263,230.702 ; 295.382,-215.037 295.382,-208.433 308.971,-194.844 308.971,-192.304 312.464,-188.811 ; 301.264,302.076 301.264,307.918 ; 302.153,280.867 302.153,271.723 306.471,267.405 ; 309.011,221.558 309.011,228.162 322.6,241.751 322.6,244.291 326.092,247.784 ; 415.808,-80.036 421.777,-80.036 426.476,-84.735 444.129,-84.735 447.304,-87.91 447.304,-99.721 ; 420.634,-214.148 420.634,-205.893 ; 428.635,-134.519 428.635,-128.677 ; 429.437,356.559 435.406,356.559 440.105,351.86 457.758,351.86 460.933,348.685 460.933,336.874 ; 429.524,-155.728 429.524,-164.872 433.842,-169.19 ; 434.263,222.447 434.263,230.702 ; 436.382,-215.037 436.382,-208.433 449.971,-194.844 449.971,-192.304 453.464,-188.811 ; 442.264,302.076 442.264,307.918 ; 443.153,280.867 443.153,271.723 447.471,267.405 ; 450.011,221.558 450.011,228.162 463.6,241.751 463.6,244.291 467.092,247.784
  lines w1.7: 275.951,-181.509 304.653,-181.509 ; 276.205,-184.811 276.205,-196.114 284.587,-204.496 284.587,-213.513 ; 289.58,255.086 318.282,255.086 ; 289.834,251.784 289.834,240.481 298.216,232.099 298.216,223.082 ; 416.951,-181.509 445.653,-181.509 ; 417.205,-184.811 417.205,-196.114 425.587,-204.496 425.587,-213.513 ; 430.58,255.086 459.282,255.086 ; 430.834,251.784 430.834,240.481 439.216,232.099 439.216,223.082
  lines w3: 285.349,-181.255 285.349,-170.714 ; 298.978,255.34 298.978,265.881 ; 426.349,-181.255 426.349,-170.714 ; 439.978,255.34 439.978,265.881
